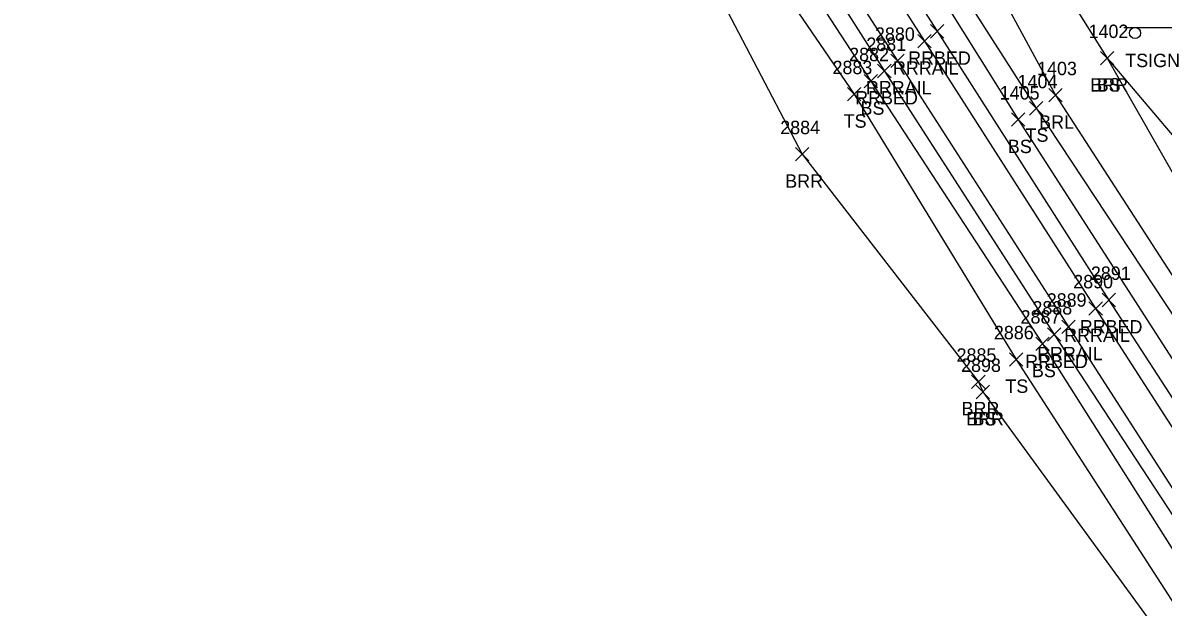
# Model space of a CAD drawing. Extents: x 1505656 to 1508446, y 700805 to 703031.
# Drawn here: x 1506055.9 to 1506226.3, y 702186 to 702273.3 of the extents above; entities that cross this region are included whole.
import ezdxf

# ---------------------------------------------------------------- set-up
doc = ezdxf.new("R2010")
doc.units = 0
for name, color, linetype in [('L_A', 7, 'Continuous'), ('L_I', 7, 'Continuous'), ('L_TIC', 7, 'Continuous'), ('LABL', 7, 'Continuous'), ('LELB', 7, 'Continuous'), ('R_A', 7, 'Continuous'), ('R_I', 7, 'Continuous'), ('R_TIC', 7, 'Continuous'), ('RR', 7, 'Continuous'), ('RRB', 7, 'Continuous'), ('S_A', 7, 'Continuous'), ('SSGN', 7, 'Continuous')]:
    doc.layers.add(name, color=color, linetype=linetype)

msp = doc.modelspace()

# ---------------------------------------------------------------- linework, layer by layer
at = {"layer": 'L_TIC'}
for points in [[(1506216.94, 702267), (1506218.94, 702269)], [(1506218.94, 702267), (1506216.94, 702269)], [(1506216.94, 702267), (1506218.94, 702269)], [(1506218.94, 702267), (1506216.94, 702269)], [(1506181.64, 702263.54), (1506183.64, 702265.54)], [(1506183.64, 702263.54), (1506181.64, 702265.54)], [(1506179.15, 702261.6), (1506181.15, 702263.6)], [(1506181.15, 702261.6), (1506179.15, 702263.6)], [(1506209.24, 702261.45), (1506211.24, 702263.45)], [(1506211.24, 702261.45), (1506209.24, 702263.45)], [(1506206.33, 702259.5), (1506208.33, 702261.5)], [(1506208.33, 702259.5), (1506206.33, 702261.5)], [(1506203.66, 702257.81), (1506205.66, 702259.81)], [(1506205.66, 702257.81), (1506203.66, 702259.81)], [(1506171.34, 702252.64), (1506173.34, 702254.64)], [(1506173.34, 702252.64), (1506171.34, 702254.64)], [(1506207.26, 702224.34), (1506209.26, 702226.34)], [(1506209.26, 702224.34), (1506207.26, 702226.34)], [(1506203.32, 702222), (1506205.32, 702224)], [(1506205.32, 702222), (1506203.32, 702224)], [(1506197.69, 702218.65), (1506199.69, 702220.65)], [(1506199.69, 702218.65), (1506197.69, 702220.65)], [(1506198.37, 702217.13), (1506200.37, 702219.13)], [(1506200.37, 702217.13), (1506198.37, 702219.13)], [(1506198.37, 702217.13), (1506200.37, 702219.13)], [(1506200.37, 702217.13), (1506198.37, 702219.13)]]:
    msp.add_lwpolyline(points, dxfattribs=at)
at = {"layer": 'LABL'}
for points in [[(1506097.89, 702451.48), (1506093.59, 702448.31), (1506114.07, 702419.3), (1506137.72, 702376.05), (1506165.52, 702335.14), (1506176.55, 702314.38), (1506188.56, 702296.46), (1506197.64, 702285.72), (1506210.24, 702262.45), (1506236.39, 702222.1), (1506262.97, 702180.71), (1506287.88, 702142.77), (1506318.3, 702098.36), (1506343.91, 702058.61), (1506370.15, 702020.94), (1506392.92, 701982.02), (1506408.75, 701957.63), (1506404.6, 701955.65), (1506415.57, 701943.72), (1506429.75, 701925.56), (1506437.71, 701917.37), (1506453.7, 701897.97), (1506473.58, 701870.51), (1506501.09, 701827)], [(1506097.89, 702451.48), (1506119.33, 702422.59), (1506147.14, 702381.23), (1506170.74, 702339.27), (1506181.05, 702317.33), (1506195.31, 702300.85), (1506204.63, 702289.22), (1506217.94, 702268), (1506249.76, 702230.45), (1506275.61, 702192.02), (1506301.13, 702151.48), (1506333.13, 702110.45), (1506362.68, 702074.77), (1506393.24, 702036.24), (1506419.01, 702002.4), (1506440.79, 701985.8), (1506459.2, 701943.61), (1506474.51, 701912.21), (1506491.96, 701880.66), (1506505.67, 701860.23), (1506521.4, 701845.88), (1506529.18, 701832.12), (1506516.38, 701828.81), (1506501.09, 701827)], [(1506077.93, 702415.16), (1506101.28, 702377.35), (1506130.25, 702337.83), (1506148.9, 702298.51), (1506172.34, 702253.64), (1506198.69, 702219.65), (1506199.37, 702218.13)]]:
    msp.add_lwpolyline(points, dxfattribs=at)
at = {"layer": 'LELB'}
for points in [[(1505941.54, 702671.13), (1505960.91, 702641.21), (1505983.85, 702606.41), (1506009.66, 702565.58), (1506036.17, 702525.55), (1506062.35, 702483.61), (1506087.3, 702443.66), (1506107.03, 702410.49), (1506132.1, 702372.93), (1506158.96, 702331.11), (1506171.73, 702310.51), (1506183.6, 702292.09), (1506190.68, 702281.13), (1506204.66, 702258.81), (1506230.37, 702218.88), (1506257.75, 702177.44), (1506282.28, 702138.54), (1506311.28, 702093.48), (1506337.33, 702051.88), (1506360.11, 702017.94), (1506385.57, 701975.18)], [(1506083.02, 702417.83), (1506106.98, 702380.08), (1506133.95, 702340.37), (1506156.69, 702304.37), (1506182.64, 702264.54), (1506208.26, 702225.34), (1506233.07, 702186.13)], [(1506130.25, 702337.83), (1506153.31, 702301.79), (1506180.15, 702262.6), (1506204.32, 702223), (1506229.62, 702183.9), (1506252.28, 702148.49), (1506276.64, 702107.67), (1506307.58, 702063.75), (1506332.81, 702021.45)], [(1506188.56, 702296.46), (1506192.93, 702283.04), (1506207.33, 702260.5), (1506233.6, 702220.79), (1506259.91, 702179.3), (1506284.93, 702140.8), (1506313.83, 702095.76), (1506340.97, 702055.87), (1506361.09, 702019.6), (1506387.67, 701976.73), (1506404.6, 701955.65)], [(1506217.94, 702268), (1506241.75, 702226.26), (1506266.61, 702184.29), (1506291.5, 702144.91), (1506326.97, 702105.86), (1506352.66, 702068.74), (1506380.93, 702030.46), (1506410.26, 701994.34), (1506417.88, 701971.26), (1506422.76, 701954.38), (1506429.75, 701925.56), (1506435.03, 701911.2)], [(1506199.37, 702218.13), (1506226.59, 702180.83), (1506249.6, 702145.67), (1506273.74, 702105.75), (1506305.4, 702061.94), (1506332.81, 702021.45)]]:
    msp.add_lwpolyline(points, dxfattribs=at)
at = {"layer": 'R_TIC'}
for points in [[(1506189.64, 702269.53), (1506191.64, 702271.53)], [(1506191.64, 702269.53), (1506189.64, 702271.53)], [(1506191.55, 702271), (1506193.55, 702273)], [(1506193.55, 702271), (1506191.55, 702273)], [(1506185.59, 702266.58), (1506187.59, 702268.58)], [(1506187.59, 702266.58), (1506185.59, 702268.58)], [(1506183.64, 702265.07), (1506185.64, 702267.07)], [(1506185.64, 702265.07), (1506183.64, 702267.07)], [(1506217.21, 702230.87), (1506219.21, 702232.87)], [(1506219.21, 702230.87), (1506217.21, 702232.87)], [(1506215.22, 702229.61), (1506217.22, 702231.61)], [(1506217.22, 702229.61), (1506215.22, 702231.61)], [(1506211.18, 702226.87), (1506213.18, 702228.87)], [(1506213.18, 702226.87), (1506211.18, 702228.87)], [(1506209.03, 702225.7), (1506211.03, 702227.7)], [(1506211.03, 702225.7), (1506209.03, 702227.7)]]:
    msp.add_lwpolyline(points, dxfattribs=at)
at = {"layer": 'RR'}
for points in [[(1506092.27, 702423.67), (1506116.35, 702386.15), (1506142.43, 702345.62), (1506165.46, 702309.78), (1506190.64, 702270.53), (1506216.22, 702230.61), (1506241.14, 702191.91)], [(1506088.05, 702421.09), (1506112.25, 702383.56), (1506138.21, 702342.92), (1506160.78, 702307.65), (1506186.59, 702267.58), (1506212.18, 702227.87), (1506237.14, 702189.06)]]:
    msp.add_lwpolyline(points, dxfattribs=at)
at = {"layer": 'RRB'}
for points in [[(1506094.28, 702424.69), (1506118.37, 702387.42), (1506144.41, 702346.71), (1506167.32, 702311.2), (1506192.55, 702272), (1506218.21, 702231.87), (1506243.42, 702192.99)], [(1506086.23, 702420.33), (1506109.91, 702382.14), (1506136.76, 702341.78), (1506159.04, 702306.27), (1506184.64, 702266.07), (1506210.03, 702226.7), (1506235.37, 702188.01)]]:
    msp.add_lwpolyline(points, dxfattribs=at)
at = {"layer": 'SSGN'}
for p, q in [((1506220.45, 702272.58), (1506229.05, 702272.58)), ((1506224.47, 702271.67), (1506224.47, 702271.67))]:
    msp.add_line(p, q, dxfattribs=at)
msp.add_circle((1506222.11, 702271.74), 0.833, dxfattribs=at)

# ---------------------------------------------------------------- texts
at = {"layer": 'L_A'}
for s, p in [('BRR', (1506215.42, 702263)), ('BS', (1506216.38, 702263)), ('BS', (1506181.08, 702259.54)), ('TS', (1506178.56, 702257.6)), ('BRL', (1506207.78, 702257.45)), ('TS', (1506205.74, 702255.5)), ('BS', (1506203.1, 702253.81)), ('BRR', (1506169.83, 702248.64)), ('BS', (1506206.7, 702220.34)), ('TS', (1506202.73, 702218)), ('BRR', (1506196.18, 702214.65)), ('BRR', (1506196.86, 702213.13)), ('BS', (1506197.82, 702213.13))]:
    msp.add_text(s, height=2, dxfattribs=at).set_placement(p)
at = {"layer": 'L_I'}
for s, p in [('1402', (1506215.16, 702271)), ('1402', (1506215.16, 702271)), ('2882', (1506179.38, 702267.54)), ('2883', (1506176.89, 702265.6)), ('1403', (1506207.47, 702265.45)), ('1404', (1506204.56, 702263.5)), ('1405', (1506201.89, 702261.81)), ('2884', (1506169.08, 702256.64)), ('2887', (1506205, 702228.34)), ('2886', (1506201.01, 702226)), ('2885', (1506195.43, 702222.65)), ('2898', (1506196.11, 702221.13)), ('2898', (1506196.11, 702221.13))]:
    msp.add_text(s, height=2, dxfattribs=at).set_placement(p)
at = {"layer": 'R_A'}
for s, p in [('RRBED', (1506188.2, 702267)), ('RRRAIL', (1506185.93, 702265.53)), ('RRBED', (1506180.28, 702261.07)), ('RRRAIL', (1506181.88, 702262.58)), ('RRBED', (1506213.85, 702226.87)), ('RRRAIL', (1506211.51, 702225.61)), ('RRRAIL', (1506207.47, 702222.87)), ('RRBED', (1506205.68, 702221.7))]:
    msp.add_text(s, height=2, dxfattribs=at).set_placement(p)
at = {"layer": 'R_I'}
for s, p in [('2880', (1506183.24, 702270.58)), ('2881', (1506181.95, 702269.07)), ('2891', (1506215.51, 702234.87)), ('2890', (1506212.87, 702233.61)), ('2889', (1506208.91, 702230.87)), ('2888', (1506206.77, 702229.7))]:
    msp.add_text(s, height=2, dxfattribs=at).set_placement(p)
at = {"layer": 'S_A'}
msp.add_text('TSIGN', height=2, dxfattribs=at).set_placement((1506220.65, 702266.65))

doc.saveas('drawing.dxf')
